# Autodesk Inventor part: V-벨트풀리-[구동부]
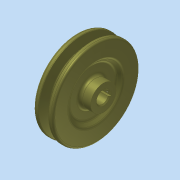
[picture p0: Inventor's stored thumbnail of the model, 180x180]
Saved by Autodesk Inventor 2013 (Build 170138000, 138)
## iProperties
Company: 한국ATC센터
Created: 2014-02
Part Number: V-벨트풀리-[구동부]
Document SubType Name: Modeling
Designer: KYOUNG IL JANG
Density: 7.25 g/cm^3
Mass: 594.654 g
Surface Area: 210.328 cm^2
Volume: 82.0213 cm^3
Material: 주철
Vendor: CBT Solutions
Author: KYOUNG IL JANG
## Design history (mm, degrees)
sketch "스케치1"
  geometry: L1 (-13, 0)-(13, 0); L2 (-13, 0)-(-13, 12.5); L3 (-13, 12.5)-(-9, 12.5); L4 (-9, 12.5)-(-9, 23); L5 (-9, 23)-(-13, 27); L6 (-13, 27)-(-13, 42.7); L7 (-13, 42.7)-(-8.325, 42.7); L8 (-8.325, 42.7)-(-5.574, 33.7); L9 (-5.574, 33.7)-(-1.426, 33.7); L10 (-1.426, 33.7)-(1.325, 42.7); L11 (1.325, 42.7)-(6, 42.7); L12 (6, 42.7)-(6, 27); L13 (6, 27)-(2, 23); L14 (2, 23)-(2, 12.5); L15 (2, 12.5)-(13, 12.5); L16 (13, 12.5)-(13, 0); L17 (-7.5, 40)-(0.5, 40); 2 further points
  constraints: 34 end point, 6 parallel, 5 collinear, 5 equal length, 4 perpendicular, 2 point on line, 1 coincident, 1 horizontal, 1 midpoint
  dimensions: "d0" = 26 distance of L1.start L1.end; "d1" = 2.7 distance between parallel lines of L7 L17; "d2" = 6.3 distance between parallel lines of L9 L17; "d3" = 8 distance of L17.start L17.end; "d4" = 34 deg angle of L10 L8; "d5" = 19 distance between parallel lines of L12 L6; "d7" = 25 diameter of L15 L1; "d8" = 46 diameter of L13.end L1; "d9" = 54 diameter of L12.end L1; "d10" = 4 distance between parallel lines of L2 L4; "d11" = 80 diameter of L17 L1
revolve "회전1" sketch "스케치1" stored, may be unused: angle "d12" = 90 deg
sketch "스케치2"
  geometry: L1 (-2, 5.657)-(-2, 7.8); L2 (-2, 7.8)-(2, 7.8); L3 (2, 7.8)-(2, 5.657); A1 r 6 centre (0, 0) between (-2, 5.657) and (2, 5.657); 1 further point
  constraints: 6 end point, 2 parallel, 2 point on circle, 1 centre point, 1 coincident, 1 perpendicular, 1 vertical
  dimensions: "d13" = 12 diameter of A1; "d14" = 13.8 dimension on A1 L2; "d15" = 4 distance of L1.end L2.end
extrude "돌출1" cut sketch "스케치2" stored distance "d16" = 10; taper "d17" = 0 deg
node "작업 평면1"
sketch "스케치3"
  geometry: L1 (-5.5, 12.5)-(-5.5, -12.5) reference; 3 further points
  constraints: 1 horizontal alignment, 1 midpoint
  dimensions: "d18" = 4 distance from line of point (-1.5, 0) L1
hole "구멍1" sketch "스케치3" at (-1.5, 0) diameter "d19" = 2.459; stored, may be unused: countersink angle "d23" = 90 deg, drill point angle "d25" = 118 deg; dims "d20" = 6, "d21" = 4, "d22" = 2, "d24" = 8
fillet "모깎기1" dims "d26" = 2, "d27" = 0.5, "d28" = 1, "d29" = 3
chamfer "모따기1" distance "d30" = 1; stored, may be unused: second distance "d31" = 2, angle "d32" = 45 deg
node "솔리드1"
